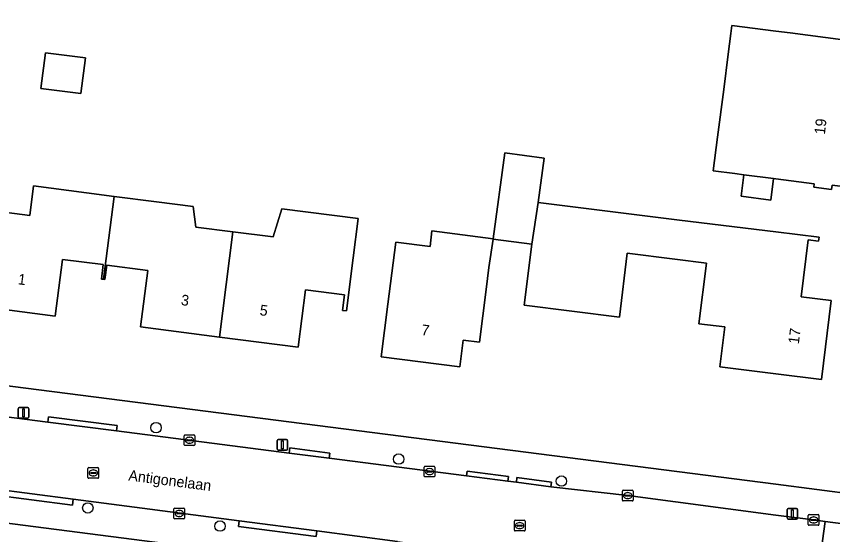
# Model space of a CAD drawing. Extents: x 162184 to 163154, y 385507 to 386516.
# Drawn here: x 162428.7 to 162505.3, y 385954.9 to 386003.6 of the extents above; entities that cross this region are included whole.
import ezdxf

# ---------------------------------------------------------------- set-up
doc = ezdxf.new("R2010")
doc.units = 0
for name, color, linetype in [('IMGEO_Boom', 7, 'Continuous'), ('IMGEO_Erf', 7, 'Continuous'), ('IMGEO_Kolk', 7, 'Continuous'), ('IMGEO_Lichtmast', 7, 'Continuous'), ('IMGEO_Openbare_ruimte_label', 7, 'Continuous'), ('IMGEO_Pand', 7, 'Continuous'), ('IMGEO_Pand_nummerreeks', 7, 'Continuous'), ('IMGEO_Rijbaan_lokaal_open', 7, 'Continuous'), ('IMGEO_Rioolput', 7, 'Continuous'), ('IMGEO_Voetpad_open', 7, 'Continuous')]:
    doc.layers.add(name, color=color, linetype=linetype)

msp = doc.modelspace()

# ---------------------------------------------------------------- linework, layer by layer
at = {"layer": 'IMGEO_Boom'}
for centre in [(162441.836, 385964.958), (162464.604, 385962.014), (162479.874, 385959.945), (162435.436, 385957.424), (162447.84, 385955.726)]:
    msp.add_circle(centre, 0.489, dxfattribs=at)
at = {"layer": 'IMGEO_Erf'}
for points in [[(162502.815, 385946.351), (162500, 385946.714), (162403.833, 385959.101), (162386.496, 385961.334), (162390.703, 386000), (162394.706, 386036.792)], [(162422.348, 386033.225), (162418.561, 386004.261), (162419.289, 386004.166), (162419.601, 386006.591), (162422.654, 386006.198), (162422.341, 386003.767), (162423.388, 386003.63), (162422.904, 386000), (162419.894, 385976.404), (162419.079, 385970.015), (162500, 385959.644), (162507.69, 385958.658)], [(162506.524, 385987.556), (162505.265, 385987.719), (162505.213, 385987.312), (162503.544, 385987.527), (162503.585, 385987.844), (162500, 385988.308), (162499.774, 385988.337), (162499.512, 385986.31), (162496.733, 385986.669), (162496.995, 385988.696), (162496.14, 385988.806), (162494.114, 385989.068), (162494.519, 385992.203), (162495.098, 385996.685), (162495.526, 386000), (162495.776, 386001.941), (162495.875, 386002.705), (162500, 386002.173), (162501.337, 386002), (162506.295, 386001.359)], [(162426.115, 385985.358), (162429.99, 385984.86), (162430.347, 385987.634), (162435.307, 385986.996), (162437.909, 385986.659), (162441.873, 385986.152), (162445.307, 385985.711), (162445.556, 385983.782), (162449.05, 385983.333), (162452.821, 385982.848), (162453.648, 385985.493), (162460.813, 385984.572), (162460.338, 385980.878), (162459.701, 385975.918), (162459.322, 385975.967), (162459.511, 385977.432), (162455.856, 385977.902), (162455.163, 385972.509), (162447.78, 385973.458), (162440.393, 385974.408), (162441.075, 385979.707), (162437.221, 385980.202), (162437.048, 385978.857), (162436.893, 385978.877), (162436.709, 385978.901), (162436.883, 385980.259), (162433.065, 385980.75), (162432.38, 385975.424), (162424.961, 385976.378)]]:
    msp.add_lwpolyline(points, dxfattribs=at)
for points in [[(162435.215, 385999.655), (162434.783, 385996.302), (162431.04, 385996.784), (162431.472, 386000.137)], [(162474.553, 385990.745), (162478.259, 385990.251), (162477.702, 385986.078), (162490.957, 385984.441), (162500, 385983.324), (162504.054, 385982.823), (162504.009, 385982.457), (162503.022, 385982.579), (162502.362, 385977.237), (162505.195, 385976.887), (162504.28, 385969.475), (162500, 385970.004), (162494.75, 385970.652), (162495.214, 385974.41), (162492.774, 385974.711), (162493.477, 385980.408), (162490.505, 385980.775), (162486.054, 385981.325), (162485.315, 385975.341), (162476.383, 385976.444), (162477.09, 385982.17), (162473.473, 385982.652), (162473.071, 385979.979), (162472.813, 385977.936), (162472.186, 385972.975), (162470.644, 385973.17), (162470.327, 385970.661), (162462.964, 385971.592), (162463.591, 385976.553), (162464.328, 385982.378), (162467.544, 385981.971), (162467.727, 385983.419), (162473.479, 385982.691)]]:
    msp.add_lwpolyline(points, close=True, dxfattribs=at)
at = {"layer": 'IMGEO_Kolk'}
for p, q in [((162444.472, 385963.355), (162444.472, 385964.207)), ((162444.547, 385964.281), (162445.399, 385964.281)), ((162444.731, 385963.775), (162444.731, 385963.787)), ((162445.169, 385963.738), (162444.771, 385963.738)), ((162444.774, 385963.824), (162445.172, 385963.824)), ((162444.96, 385964.061), (162444.985, 385964.061)), ((162445.215, 385963.787), (162445.215, 385963.775)), ((162445.473, 385964.207), (162445.473, 385963.355)), ((162445.399, 385963.281), (162444.547, 385963.281)), ((162444.983, 385963.501), (162444.958, 385963.501)), ((162467.071, 385961.34), (162467.923, 385961.34)), ((162466.996, 385960.414), (162466.996, 385961.266)), ((162467.255, 385960.834), (162467.255, 385960.846)), ((162467.693, 385960.797), (162467.295, 385960.797)), ((162467.298, 385960.883), (162467.696, 385960.883)), ((162467.484, 385961.12), (162467.509, 385961.12)), ((162467.739, 385960.846), (162467.739, 385960.834)), ((162467.997, 385961.266), (162467.997, 385960.414)), ((162467.923, 385960.34), (162467.071, 385960.34)), ((162467.507, 385960.56), (162467.482, 385960.56)), ((162485.672, 385959.083), (162486.524, 385959.083)), ((162485.597, 385958.157), (162485.597, 385959.009)), ((162485.856, 385958.577), (162485.856, 385958.589)), ((162486.294, 385958.54), (162485.896, 385958.54)), ((162485.899, 385958.626), (162486.297, 385958.626)), ((162486.108, 385958.303), (162486.083, 385958.303)), ((162486.085, 385958.863), (162486.11, 385958.863)), ((162486.34, 385958.589), (162486.34, 385958.577)), ((162486.598, 385959.009), (162486.598, 385958.157)), ((162486.524, 385958.083), (162485.672, 385958.083)), ((162443.517, 385956.477), (162443.517, 385957.329)), ((162443.592, 385957.403), (162444.444, 385957.403)), ((162443.776, 385956.897), (162443.776, 385956.909)), ((162444.214, 385956.86), (162443.816, 385956.86)), ((162443.819, 385956.946), (162444.217, 385956.946)), ((162444.005, 385957.183), (162444.03, 385957.183)), ((162444.26, 385956.909), (162444.26, 385956.897)), ((162444.518, 385957.329), (162444.518, 385956.477)), ((162503.115, 385956.799), (162503.967, 385956.799)), ((162444.444, 385956.403), (162443.592, 385956.403)), ((162444.028, 385956.623), (162444.003, 385956.623)), ((162503.04, 385955.873), (162503.04, 385956.725)), ((162503.299, 385956.293), (162503.299, 385956.305)), ((162503.737, 385956.256), (162503.339, 385956.256)), ((162503.342, 385956.342), (162503.74, 385956.342)), ((162503.551, 385956.019), (162503.526, 385956.019)), ((162503.528, 385956.579), (162503.553, 385956.579)), ((162503.783, 385956.305), (162503.783, 385956.293)), ((162504.041, 385956.725), (162504.041, 385955.873)), ((162503.967, 385955.799), (162503.115, 385955.799))]:
    msp.add_line(p, q, dxfattribs=at)
for points in [[(162444.472, 385963.355), (162444.472, 385964.207)], [(162444.547, 385964.281), (162445.399, 385964.281)], [(162445.473, 385964.207), (162445.473, 385963.355)], [(162445.399, 385963.281), (162444.547, 385963.281)], [(162467.071, 385961.34), (162467.923, 385961.34)], [(162466.996, 385960.414), (162466.996, 385961.266)], [(162467.997, 385961.266), (162467.997, 385960.414)], [(162467.923, 385960.34), (162467.071, 385960.34)], [(162485.672, 385959.083), (162486.524, 385959.083)], [(162485.597, 385958.157), (162485.597, 385959.009)], [(162486.598, 385959.009), (162486.598, 385958.157)], [(162486.524, 385958.083), (162485.672, 385958.083)], [(162443.517, 385956.477), (162443.517, 385957.329)], [(162443.592, 385957.403), (162444.444, 385957.403)], [(162444.518, 385957.329), (162444.518, 385956.477)], [(162503.115, 385956.799), (162503.967, 385956.799)], [(162444.444, 385956.403), (162443.592, 385956.403)], [(162503.04, 385955.873), (162503.04, 385956.725)], [(162504.041, 385956.725), (162504.041, 385955.873)], [(162503.967, 385955.799), (162503.115, 385955.799)]]:
    msp.add_lwpolyline(points, dxfattribs=at)
for centre, radius, start, end in [((162444.549, 385964.205), 0.0765, 91.55205, 178.44795), ((162444.549, 385964.205), 0.0765, 91.55205, 178.44795), ((162444.771, 385963.784), 0.0403, 85.87752, 175.75265), ((162444.768, 385963.774), 0.0366, 178.93798, 274.71019), ((162445.172, 385963.781), 0.043, 264.86636, 352.45326), ((162445.176, 385963.786), 0.0386, 1.73085, 96.63898), ((162445.397, 385964.205), 0.0765, 1.55205, 88.44795), ((162445.397, 385964.205), 0.0765, 1.55205, 88.44795), ((162444.549, 385963.357), 0.0765, 181.55205, 268.44795), ((162444.549, 385963.357), 0.0765, 181.55205, 268.44795), ((162445.397, 385963.357), 0.0765, 271.55205, 358.44795), ((162445.397, 385963.357), 0.0765, 271.55205, 358.44795), ((162467.073, 385961.264), 0.0765, 91.55205, 178.44795), ((162467.073, 385961.264), 0.0765, 91.55205, 178.44795), ((162467.921, 385961.264), 0.0765, 1.55205, 88.44795), ((162467.921, 385961.264), 0.0765, 1.55205, 88.44795), ((162467.295, 385960.843), 0.0403, 85.87752, 175.75265), ((162467.292, 385960.833), 0.0366, 178.93798, 274.71019), ((162467.696, 385960.84), 0.043, 264.86636, 352.45326), ((162467.7, 385960.845), 0.0386, 1.73085, 96.63898), ((162467.073, 385960.416), 0.0765, 181.55205, 268.44795), ((162467.073, 385960.416), 0.0765, 181.55205, 268.44795), ((162467.921, 385960.416), 0.0765, 271.55205, 358.44795), ((162467.921, 385960.416), 0.0765, 271.55205, 358.44795), ((162485.674, 385959.007), 0.0765, 91.55205, 178.44795), ((162485.674, 385959.007), 0.0765, 91.55205, 178.44795), ((162486.522, 385959.007), 0.0765, 1.55205, 88.44795), ((162486.522, 385959.007), 0.0765, 1.55205, 88.44795), ((162485.896, 385958.586), 0.0403, 85.87752, 175.75265), ((162485.893, 385958.576), 0.0366, 178.93798, 274.71019), ((162486.297, 385958.583), 0.043, 264.86636, 352.45326), ((162486.301, 385958.588), 0.0386, 1.73085, 96.63898), ((162485.674, 385958.159), 0.0765, 181.55205, 268.44795), ((162485.674, 385958.159), 0.0765, 181.55205, 268.44795), ((162486.522, 385958.159), 0.0765, 271.55205, 358.44795), ((162486.522, 385958.159), 0.0765, 271.55205, 358.44795), ((162443.594, 385957.327), 0.0765, 91.55205, 178.44795), ((162443.594, 385957.327), 0.0765, 91.55205, 178.44795), ((162443.816, 385956.906), 0.0403, 85.87752, 175.75265), ((162443.813, 385956.896), 0.0366, 178.93798, 274.71019), ((162444.217, 385956.903), 0.043, 264.86636, 352.45326), ((162444.221, 385956.908), 0.0386, 1.73085, 96.63898), ((162444.442, 385957.327), 0.0765, 1.55205, 88.44795), ((162444.442, 385957.327), 0.0765, 1.55205, 88.44795), ((162503.117, 385956.723), 0.0765, 91.55205, 178.44795), ((162503.117, 385956.723), 0.0765, 91.55205, 178.44795), ((162503.965, 385956.723), 0.0765, 1.55205, 88.44795), ((162503.965, 385956.723), 0.0765, 1.55205, 88.44795), ((162443.594, 385956.479), 0.0765, 181.55205, 268.44795), ((162443.594, 385956.479), 0.0765, 181.55205, 268.44795), ((162444.442, 385956.479), 0.0765, 271.55205, 358.44795), ((162444.442, 385956.479), 0.0765, 271.55205, 358.44795), ((162503.339, 385956.302), 0.0403, 85.87752, 175.75265), ((162503.336, 385956.292), 0.0366, 178.93798, 274.71019), ((162503.74, 385956.299), 0.043, 264.86636, 352.45326), ((162503.744, 385956.304), 0.0386, 1.73085, 96.63898), ((162503.117, 385955.875), 0.0765, 181.55205, 268.44795), ((162503.117, 385955.875), 0.0765, 181.55205, 268.44795), ((162503.965, 385955.875), 0.0765, 271.55205, 358.44795), ((162503.965, 385955.875), 0.0765, 271.55205, 358.44795)]:
    msp.add_arc(centre, radius, start, end, dxfattribs=at)
for centre, major_axis, ratio, start_param, end_param in [((162444.959, 385963.781), (-0.387, 0.002), 0.722429, 4.712389, 7.853982), ((162444.984, 385963.781), (-0.39, 0.002), 0.717154, 1.570796, 4.712389), ((162467.483, 385960.84), (-0.387, 0.002), 0.722429, 4.712389, 7.853982), ((162467.508, 385960.84), (-0.39, 0.002), 0.717154, 1.570796, 4.712389), ((162486.084, 385958.583), (-0.387, 0.002), 0.722429, 4.712389, 7.853982), ((162486.109, 385958.583), (-0.39, 0.002), 0.717154, 1.570796, 4.712389), ((162444.004, 385956.903), (-0.387, 0.002), 0.722429, 4.712389, 7.853982), ((162444.029, 385956.903), (-0.39, 0.002), 0.717154, 1.570796, 4.712389), ((162503.527, 385956.299), (-0.387, 0.002), 0.722429, 4.712389, 7.853982), ((162503.552, 385956.299), (-0.39, 0.002), 0.717154, 1.570796, 4.712389)]:
    msp.add_ellipse(centre, major_axis=major_axis, ratio=ratio, start_param=start_param, end_param=end_param, dxfattribs=at)
at = {"layer": 'IMGEO_Lichtmast'}
for p, q in [((162428.904, 385965.939), (162428.904, 385966.739)), ((162428.904, 385966.739), (162428.904, 385965.939)), ((162429.004, 385966.839), (162429.794, 385966.839)), ((162429.794, 385966.839), (162429.004, 385966.839)), ((162429.894, 385966.739), (162429.894, 385965.939)), ((162429.894, 385965.939), (162429.894, 385966.739)), ((162429.794, 385965.839), (162429.004, 385965.839)), ((162429.004, 385965.839), (162429.794, 385965.839)), ((162453.196, 385962.942), (162453.196, 385963.742)), ((162453.196, 385963.742), (162453.196, 385962.942)), ((162453.296, 385963.842), (162454.086, 385963.842)), ((162454.086, 385963.842), (162453.296, 385963.842)), ((162454.186, 385963.742), (162454.186, 385962.942)), ((162454.186, 385962.942), (162454.186, 385963.742)), ((162454.086, 385962.842), (162453.296, 385962.842)), ((162453.296, 385962.842), (162454.086, 385962.842)), ((162501.05, 385956.484), (162501.05, 385957.284)), ((162501.05, 385957.284), (162501.05, 385956.484)), ((162501.15, 385957.384), (162501.94, 385957.384)), ((162501.94, 385957.384), (162501.15, 385957.384)), ((162502.04, 385957.284), (162502.04, 385956.484)), ((162502.04, 385956.484), (162502.04, 385957.284)), ((162501.94, 385956.384), (162501.15, 385956.384)), ((162501.15, 385956.384), (162501.94, 385956.384))]:
    msp.add_line(p, q, dxfattribs=at)
for points in [[(162429.324, 385966.714), (162429.474, 385966.714), (162429.474, 385965.964), (162429.324, 385965.964), (162429.324, 385966.714)], [(162453.616, 385963.717), (162453.766, 385963.717), (162453.766, 385962.967), (162453.616, 385962.967), (162453.616, 385963.717)], [(162501.47, 385957.259), (162501.62, 385957.259), (162501.62, 385956.509), (162501.47, 385956.509), (162501.47, 385957.259)]]:
    msp.add_lwpolyline(points, dxfattribs=at)
for centre, start, end in [((162429.004, 385966.739), 90, 180), ((162429.004, 385966.739), 90, 180), ((162429.794, 385966.739), 0, 90), ((162429.794, 385966.739), 360, 90), ((162429.004, 385965.939), 180, 270), ((162429.004, 385965.939), 180, 270), ((162429.794, 385965.939), 270, 0), ((162429.794, 385965.939), 270, 0), ((162453.296, 385963.742), 90, 180), ((162453.296, 385963.742), 90, 180), ((162454.086, 385963.742), 0, 90), ((162454.086, 385963.742), 360, 90), ((162453.296, 385962.942), 180, 270), ((162453.296, 385962.942), 180, 270), ((162454.086, 385962.942), 270, 0), ((162454.086, 385962.942), 270, 0), ((162501.15, 385957.284), 90, 180), ((162501.15, 385957.284), 90, 180), ((162501.94, 385957.284), 0, 90), ((162501.94, 385957.284), 360, 90), ((162501.15, 385956.484), 180, 270), ((162501.15, 385956.484), 180, 270), ((162501.94, 385956.484), 270, 0), ((162501.94, 385956.484), 270, 0)]:
    msp.add_arc(centre, 0.1, start, end, dxfattribs=at)
at = {"layer": 'IMGEO_Pand'}
msp.add_lwpolyline([(162506.295, 386001.359), (162501.337, 386002), (162500, 386002.173), (162495.875, 386002.705), (162495.776, 386001.941), (162495.526, 386000), (162495.098, 385996.685), (162494.519, 385992.203), (162494.114, 385989.068), (162496.14, 385988.806), (162496.995, 385988.696), (162499.774, 385988.337), (162500, 385988.308), (162503.585, 385987.844), (162503.544, 385987.527), (162505.213, 385987.312), (162505.265, 385987.719), (162506.524, 385987.556)], dxfattribs=at)
for points in [[(162435.215, 385999.655), (162431.472, 386000.137), (162431.04, 385996.784), (162434.783, 385996.302)], [(162478.259, 385990.251), (162474.553, 385990.745), (162473.479, 385982.691), (162473.473, 385982.652), (162477.09, 385982.17), (162477.702, 385986.078)], [(162499.774, 385988.337), (162496.995, 385988.696), (162496.733, 385986.669), (162499.512, 385986.31)], [(162437.909, 385986.659), (162435.307, 385986.996), (162430.347, 385987.634), (162429.99, 385984.86), (162426.115, 385985.358), (162424.961, 385976.378), (162432.38, 385975.424), (162433.065, 385980.75), (162436.883, 385980.259), (162436.709, 385978.901), (162436.893, 385978.877)], [(162436.893, 385978.877), (162437.048, 385978.857), (162437.221, 385980.202), (162441.075, 385979.707), (162440.393, 385974.408), (162447.78, 385973.458), (162449.05, 385983.333), (162445.556, 385983.782), (162445.307, 385985.711), (162441.873, 385986.152), (162437.909, 385986.659)], [(162477.09, 385982.17), (162476.383, 385976.444), (162485.315, 385975.341), (162486.054, 385981.325), (162490.505, 385980.775), (162493.477, 385980.408), (162492.774, 385974.711), (162495.214, 385974.41), (162494.75, 385970.652), (162500, 385970.004), (162504.28, 385969.475), (162505.195, 385976.887), (162502.362, 385977.237), (162503.022, 385982.579), (162504.009, 385982.457), (162504.054, 385982.823), (162500, 385983.324), (162490.957, 385984.441), (162477.702, 385986.078)], [(162447.78, 385973.458), (162455.163, 385972.509), (162455.856, 385977.902), (162459.511, 385977.432), (162459.322, 385975.967), (162459.701, 385975.918), (162460.338, 385980.878), (162460.813, 385984.572), (162453.648, 385985.493), (162452.821, 385982.848), (162449.05, 385983.333)], [(162472.813, 385977.936), (162473.071, 385979.979), (162473.473, 385982.652), (162473.479, 385982.691), (162467.727, 385983.419), (162467.544, 385981.971), (162464.328, 385982.378), (162463.591, 385976.553), (162462.964, 385971.592), (162470.327, 385970.661), (162470.644, 385973.17), (162472.186, 385972.975)]]:
    msp.add_lwpolyline(points, close=True, dxfattribs=at)
at = {"layer": 'IMGEO_Rijbaan_lokaal_open'}
msp.add_lwpolyline([(162438.129, 385964.652), (162431.689, 385965.478), (162404.689, 385968.943), (162404.219, 385962.125), (162411.785, 385961.141), (162426.343, 385959.248), (162434.07, 385958.243), (162449.651, 385956.216), (162456.91, 385955.272), (162464.48, 385954.288), (162469.536, 385953.63), (162486.007, 385951.511), (162503.658, 385949.12), (162504.634, 385956.15), (162503.537, 385956.297), (162500, 385956.76), (162486.094, 385958.582), (162478.889, 385959.402), (162475.648, 385959.837), (162474.856, 385959.939), (162470.976, 385960.437), (162458.086, 385962.091), (162454.319, 385962.574)], close=True, dxfattribs=at)
msp.add_lwpolyline([(162508.728, 385955.623), (162504.634, 385956.15), (162503.658, 385949.12)], dxfattribs=at)
at = {"layer": 'IMGEO_Rioolput'}
for p, q in [((162435.448, 385960.285), (162435.448, 385961.137)), ((162435.523, 385961.211), (162436.375, 385961.211)), ((162435.707, 385960.705), (162435.707, 385960.717)), ((162436.145, 385960.668), (162435.747, 385960.668)), ((162435.75, 385960.754), (162436.148, 385960.754)), ((162435.936, 385960.991), (162435.961, 385960.991)), ((162436.191, 385960.717), (162436.191, 385960.705)), ((162436.449, 385961.137), (162436.449, 385960.285)), ((162436.375, 385960.211), (162435.523, 385960.211)), ((162435.959, 385960.431), (162435.934, 385960.431)), ((162475.456, 385955.34), (162475.456, 385956.192)), ((162475.531, 385956.266), (162476.383, 385956.266)), ((162475.944, 385956.046), (162475.969, 385956.046)), ((162476.457, 385956.192), (162476.457, 385955.34)), ((162476.383, 385955.266), (162475.531, 385955.266)), ((162475.715, 385955.76), (162475.715, 385955.772)), ((162476.153, 385955.723), (162475.755, 385955.723)), ((162475.758, 385955.809), (162476.156, 385955.809)), ((162475.967, 385955.486), (162475.942, 385955.486)), ((162476.199, 385955.772), (162476.199, 385955.76))]:
    msp.add_line(p, q, dxfattribs=at)
for points in [[(162435.448, 385960.285), (162435.448, 385961.137)], [(162435.523, 385961.211), (162436.375, 385961.211)], [(162436.449, 385961.137), (162436.449, 385960.285)], [(162436.375, 385960.211), (162435.523, 385960.211)], [(162475.456, 385955.34), (162475.456, 385956.192)], [(162475.531, 385956.266), (162476.383, 385956.266)], [(162476.457, 385956.192), (162476.457, 385955.34)], [(162476.383, 385955.266), (162475.531, 385955.266)]]:
    msp.add_lwpolyline(points, dxfattribs=at)
for centre, radius, start, end in [((162435.525, 385961.135), 0.0765, 91.55205, 178.44795), ((162435.525, 385961.135), 0.0765, 91.55205, 178.44795), ((162435.747, 385960.714), 0.0403, 85.87752, 175.75265), ((162435.744, 385960.704), 0.0366, 178.93798, 274.71019), ((162436.148, 385960.711), 0.043, 264.86636, 352.45326), ((162436.152, 385960.716), 0.0386, 1.73085, 96.63898), ((162436.373, 385961.135), 0.0765, 1.55205, 88.44795), ((162436.373, 385961.135), 0.0765, 1.55205, 88.44795), ((162435.525, 385960.287), 0.0765, 181.55205, 268.44795), ((162435.525, 385960.287), 0.0765, 181.55205, 268.44795), ((162436.373, 385960.287), 0.0765, 271.55205, 358.44795), ((162436.373, 385960.287), 0.0765, 271.55205, 358.44795), ((162475.533, 385956.19), 0.0765, 91.55205, 178.44795), ((162475.533, 385956.19), 0.0765, 91.55205, 178.44795), ((162476.381, 385956.19), 0.0765, 1.55205, 88.44795), ((162476.381, 385956.19), 0.0765, 1.55205, 88.44795), ((162475.533, 385955.342), 0.0765, 181.55205, 268.44795), ((162475.533, 385955.342), 0.0765, 181.55205, 268.44795), ((162475.755, 385955.769), 0.0403, 85.87752, 175.75265), ((162475.752, 385955.759), 0.0366, 178.93798, 274.71019), ((162476.156, 385955.766), 0.043, 264.86636, 352.45326), ((162476.16, 385955.771), 0.0386, 1.73085, 96.63898), ((162476.381, 385955.342), 0.0765, 271.55205, 358.44795), ((162476.381, 385955.342), 0.0765, 271.55205, 358.44795)]:
    msp.add_arc(centre, radius, start, end, dxfattribs=at)
for centre, major_axis, ratio, start_param, end_param in [((162435.935, 385960.711), (-0.387, 0.002), 0.722429, 4.712389, 7.853982), ((162435.96, 385960.711), (-0.39, 0.002), 0.717154, 1.570796, 4.712389), ((162475.943, 385955.766), (-0.387, 0.002), 0.722429, 4.712389, 7.853982), ((162475.968, 385955.766), (-0.39, 0.002), 0.717154, 1.570796, 4.712389)]:
    msp.add_ellipse(centre, major_axis=major_axis, ratio=ratio, start_param=start_param, end_param=end_param, dxfattribs=at)
at = {"layer": 'IMGEO_Voetpad_open'}
for points in [[(162500, 385959.644), (162419.079, 385970.015), (162417.17, 385970.261), (162416.956, 385970.265), (162409.041, 385971.697), (162401.718, 385972.466), (162400.227, 385971.561)], [(162404.689, 385968.943), (162431.689, 385965.478), (162431.747, 385965.978), (162438.188, 385965.158), (162438.129, 385964.652), (162454.319, 385962.574), (162454.376, 385963.056), (162458.142, 385962.564), (162458.086, 385962.091), (162470.976, 385960.437), (162471.029, 385960.881), (162474.908, 385960.374), (162474.856, 385959.939), (162475.648, 385959.837), (162475.699, 385960.271), (162478.945, 385959.861), (162478.889, 385959.402), (162486.094, 385958.582), (162500, 385956.76), (162503.537, 385956.297), (162504.634, 385956.15), (162508.728, 385955.623), (162509.718, 385959.12)], [(162449.589, 385955.688), (162449.651, 385956.216), (162434.07, 385958.243), (162434.002, 385957.684), (162426.276, 385958.698), (162426.343, 385959.248), (162411.785, 385961.141), (162411.722, 385960.623), (162404.158, 385961.623), (162403.833, 385959.101), (162500, 385946.714), (162502.815, 385946.351)], [(162507.69, 385958.658), (162500, 385959.644)], [(162503.658, 385949.12), (162486.007, 385951.511), (162469.536, 385953.63), (162469.476, 385953.127), (162464.42, 385953.783), (162464.48, 385954.288), (162456.91, 385955.272), (162456.85, 385954.757), (162449.589, 385955.688)]]:
    msp.add_lwpolyline(points, dxfattribs=at)
for points in [[(162438.129, 385964.652), (162438.188, 385965.158), (162431.747, 385965.978), (162431.689, 385965.478)], [(162454.319, 385962.574), (162458.086, 385962.091), (162458.142, 385962.564), (162454.376, 385963.056)], [(162470.976, 385960.437), (162474.856, 385959.939), (162474.908, 385960.374), (162471.029, 385960.881)], [(162475.648, 385959.837), (162478.889, 385959.402), (162478.945, 385959.861), (162475.699, 385960.271)], [(162434.07, 385958.243), (162426.343, 385959.248), (162426.276, 385958.698), (162434.002, 385957.684)], [(162449.651, 385956.216), (162449.589, 385955.688), (162456.85, 385954.757), (162456.91, 385955.272)]]:
    msp.add_lwpolyline(points, close=True, dxfattribs=at)

# ---------------------------------------------------------------- texts
at = {"layer": 'IMGEO_Openbare_ruimte_label'}
msp.add_text('Antigonelaan', height=1, rotation=352.64762, dxfattribs=at).set_placement((162439.207, 385960.011))
at = {"layer": 'IMGEO_Pand_nummerreeks'}
for s, rotation, p in [('19', 83.68049, (162504.594, 385992.421)), ('1', 352.67262, (162428.832, 385978.42)), ('3', 352.67359, (162444.134, 385976.468)), ('5', 352.67359, (162451.519, 385975.518)), ('7', 352.79219, (162466.688, 385973.661)), ('17', 82.96253, (162502.146, 385972.759))]:
    msp.add_text(s, height=1, rotation=rotation, dxfattribs=at).set_placement(p)

doc.saveas('drawing.dxf')
